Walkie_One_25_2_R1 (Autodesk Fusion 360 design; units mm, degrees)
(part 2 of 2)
sketch "Service locating rim" plane through (0, 0, -5.8) normal (0, 0, 1) x axis (1, 0, 0)
  line L1 (16, -65.4) -> (-16, -65.4)
  line L2 (41.4, 40) -> (41.4, -40)
  line L3 (-16, 65.4) -> (16, 65.4)
  line L4 (-41.4, -40) -> (-41.4, 40)
  line L5 (16, -64.4) -> (-16, -64.4)
  line L6 (40.4, 40) -> (40.4, -40)
  line L7 (-16, 64.4) -> (16, 64.4)
  line L8 (-40.4, -40) -> (-40.4, 40)
  arc A1 centre (16, -40) radius 25.4 clockwise from (41.4, -40) to (16, -65.4)
  arc A2 centre (16, 40) radius 25.4 clockwise from (16, 65.4) to (41.4, 40)
  arc A3 centre (-16, 40) radius 25.4 clockwise from (-41.4, 40) to (-16, 65.4)
  arc A4 centre (-16, -40) radius 25.4 clockwise from (-16, -65.4) to (-41.4, -40)
  arc A5 centre (16, -40) radius 24.4 clockwise from (40.4, -40) to (16, -64.4)
  arc A6 centre (16, 40) radius 24.4 clockwise from (16, 64.4) to (40.4, 40)
  arc A7 centre (-16, 40) radius 24.4 clockwise from (-40.4, 40) to (-16, 64.4)
  arc A8 centre (-16, -40) radius 24.4 clockwise from (-16, -64.4) to (-40.4, -40)
extrude "Extrude1" new body sketch "Service locating rim" along normal blind 3 bodies "rear_alignment_lip"
work_plane "WorkPlane1" AlongDistance 6.5 ExtraOffset 0
sketch "microphone_seat" plane through (0, 0, 6.5) normal (0, 0, 1) x axis (1, 0, 0)
  line L1 (26.5, -60.5) -> (17.5, -60.5)
  line L2 (28.5, -47.5) -> (28.5, -58.5)
  line L3 (17.5, -45.5) -> (26.5, -45.5)
  line L4 (15.5, -58.5) -> (15.5, -47.5)
  arc A1 centre (26.5, -58.5) radius 2 clockwise from (28.5, -58.5) to (26.5, -60.5)
  arc A2 centre (26.5, -47.5) radius 2 clockwise from (26.5, -45.5) to (28.5, -47.5)
  arc A3 centre (17.5, -47.5) radius 2 clockwise from (15.5, -47.5) to (17.5, -45.5)
  arc A4 centre (17.5, -58.5) radius 2 clockwise from (17.5, -60.5) to (15.5, -58.5)
extrude "Extrude1" new body sketch "microphone_seat" along normal blind 2 bodies "microphone_seat"
work_plane "WorkPlane2" AlongDistance 9 ExtraOffset 0
sketch "Microphone acoustic path" plane through (0, 0, 9) normal (0, 0, 1) x axis (1, 0, 0)
  circle C1 centre (22, -54) radius 1.5
  dimension "d276" diameter C1 = 3
extrude "Extrude2" cut sketch "Microphone acoustic path" against normal blind 3
work_plane "WorkPlane1" AlongDistance 14.05 ExtraOffset 0
sketch "Recessed play glyph paint boundary" plane through (0, 0, 14.05) normal (0, 0, 1) x axis (1, 0, 0)
  line L1 (-3.18, -31.94) -> (-3.18, -40.06)
  line L2 (4.46, -36) -> (-3.18, -31.94)
  line L3 (-3.18, -40.06) -> (4.46, -36)
extrude "Extrude1" new body sketch "Recessed play glyph paint boundary" along normal blind 0.035 bodies "play_glyph_paint_REFERENCE"
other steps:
create_component "CreateComponent1"
create_component "CreateComponent2"
create_component "CreateComponent3"
create_component "CreateComponent4"
create_component "CreateComponent5"
create_component "CreateComponent6"
create_component "CreateComponent7"
create_component "CreateComponent8"
create_component "CreateComponent9"
create_component "CreateComponent10"
create_component "CreateComponent11"
create_component "CreateComponent12"
create_component "CreateComponent13"
create_component "CreateComponent14"
named bodies: "structural_shell_rear", "inner_cavity_tool", "structural_shell_front", "soft_grip_rear", "skin_inner_tool", "soft_grip_front", "play_key_38mm", "ptt_paddle_72mm", "volume_plus", "volume_minus", "status_lens", "W_grille_0p8mm", "acoustic_cloth_full_area_REFERENCE", "grille_perimeter_PSA_REFERENCE", "play_switch_carrier", "speaker_edge_cradle", "rear_alignment_lip", "microphone_seat", "play_glyph_paint_REFERENCE"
